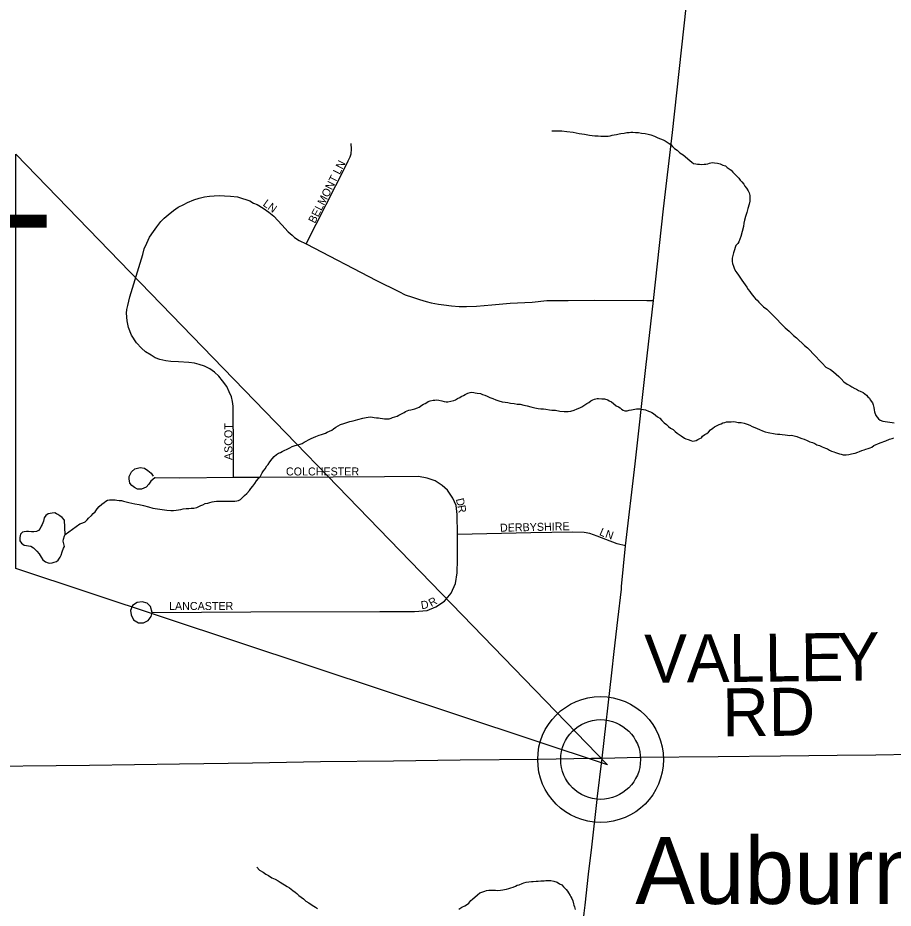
# Model space of a CAD drawing. Extents: x -10.1 to 68, y -9.5 to 29.2.
# Drawn here: x 4.482 to 5.518, y 19.418 to 20.471 of the extents above; entities that cross this region are included whole.
import ezdxf

# ---------------------------------------------------------------- set-up
doc = ezdxf.new("R2010")
doc.units = 0
for name, color, linetype in [('GM_X_County_Road', 7, 'Continuous'), ('GM_X_Minor_Lake', 7, 'Continuous'), ('GM_X_Minor_River', 7, 'Continuous'), ('GM_X_State_Route', 7, 'Continuous'), ('GM_X_Township_Road', 7, 'Continuous'), ('GM_X_Township_Road_Text', 7, 'Continuous'), ('GM_X_Township_Subdivision', 7, 'Continuous'), ('GM_X_Township_Subdivision_Text', 7, 'Continuous'), ('GM_X_Unincorporated', 7, 'Continuous'), ('GM_X_Unincorporated_Text', 7, 'Continuous'), ('SH_Data', 7, 'Continuous'), ('SH_Text', 7, 'Continuous')]:
    doc.layers.add(name, color=color, linetype=linetype)

msp = doc.modelspace()

# ---------------------------------------------------------------- linework, layer by layer
at = {"layer": 'GM_X_County_Road'}
msp.add_lwpolyline([(4.4092, 19.5855), (4.5666, 19.5872), (4.6732, 19.5887), (4.7595, 19.5899), (4.8399, 19.5914), (4.9265, 19.5923), (5.0054, 19.5936), (5.0981, 19.5945), (5.1608, 19.5955), (5.1733, 19.5955)], dxfattribs=at)
at = {"layer": 'GM_X_Minor_Lake'}
for points in [[(4.5372, 19.877), (4.5345, 19.88), (4.5318, 19.8822), (4.5295, 19.8836), (4.5276, 19.8847), (4.5256, 19.8858), (4.5226, 19.8854), (4.5177, 19.8845), (4.5151, 19.8826), (4.5132, 19.8799), (4.5122, 19.8757), (4.5107, 19.8718), (4.5096, 19.8699), (4.5085, 19.8672), (4.5063, 19.8649), (4.5041, 19.8637), (4.501, 19.8633), (4.498, 19.8632), (4.4945, 19.8635), (4.4923, 19.8638), (4.4896, 19.8634), (4.4877, 19.863), (4.4851, 19.8603), (4.4844, 19.8564), (4.4845, 19.8526), (4.4865, 19.85), (4.4896, 19.8474)], [(4.5372, 19.877), (4.5345, 19.88), (4.5318, 19.8822), (4.5295, 19.8836), (4.5276, 19.8847), (4.5256, 19.8858), (4.5226, 19.8854), (4.5177, 19.8845), (4.5151, 19.8826), (4.5132, 19.8799), (4.5122, 19.8757), (4.5107, 19.8718), (4.5096, 19.8699), (4.5085, 19.8672), (4.5063, 19.8649), (4.5041, 19.8637), (4.501, 19.8633), (4.498, 19.8632), (4.4945, 19.8635), (4.4923, 19.8638), (4.4896, 19.8634), (4.4877, 19.863), (4.4851, 19.8603), (4.4844, 19.8564), (4.4845, 19.8526), (4.4865, 19.85), (4.4896, 19.8474), (4.4972, 19.8461), (4.5007, 19.8443), (4.5026, 19.8424), (4.5045, 19.8405), (4.5073, 19.8372), (4.5085, 19.8353), (4.5096, 19.8331), (4.5116, 19.8301), (4.5147, 19.8278), (4.5178, 19.8264), (4.5197, 19.826), (4.5227, 19.8265), (4.525, 19.8273), (4.5276, 19.8281), (4.5299, 19.8297), (4.5321, 19.8332), (4.5332, 19.8358), (4.5346, 19.8397), (4.536, 19.8439), (4.5371, 19.8458), (4.5363, 19.8492), (4.5355, 19.8522), (4.5362, 19.8545), (4.5373, 19.8583), (4.538, 19.8599), (4.5372, 19.877)], [(4.4896, 19.8474), (4.4972, 19.8461), (4.5007, 19.8443), (4.5026, 19.8424), (4.5045, 19.8405), (4.5073, 19.8372), (4.5085, 19.8353), (4.5096, 19.8331), (4.5116, 19.8301), (4.5147, 19.8278), (4.5178, 19.8264), (4.5197, 19.826), (4.5227, 19.8265), (4.525, 19.8273), (4.5276, 19.8281), (4.5299, 19.8297), (4.5321, 19.8332), (4.5332, 19.8358), (4.5346, 19.8397), (4.536, 19.8439), (4.5371, 19.8458), (4.5363, 19.8492), (4.5355, 19.8522), (4.5362, 19.8545), (4.5373, 19.8583), (4.538, 19.8599), (4.5372, 19.877)]]:
    msp.add_lwpolyline(points, dxfattribs=at)
at = {"layer": 'GM_X_Minor_River'}
for points in [[(5.1136, 20.3376), (5.1163, 20.3376), (5.1201, 20.3377), (5.1254, 20.3374), (5.1315, 20.3368), (5.1388, 20.3358), (5.146, 20.3345), (5.1525, 20.3335), (5.1583, 20.3324), (5.1647, 20.3318), (5.1685, 20.3315), (5.1716, 20.3312), (5.1746, 20.3313), (5.1773, 20.3313), (5.1803, 20.3314), (5.1826, 20.3318), (5.1853, 20.3323), (5.1875, 20.3327), (5.1902, 20.3331), (5.1932, 20.334), (5.1955, 20.3344), (5.1993, 20.3349), (5.2023, 20.3357), (5.2054, 20.3357), (5.2073, 20.3358), (5.2095, 20.3358), (5.2126, 20.3355), (5.2164, 20.3356), (5.2198, 20.3349), (5.224, 20.3343), (5.2278, 20.3336), (5.2309, 20.3329), (5.2351, 20.3311), (5.239, 20.3293), (5.2424, 20.3282), (5.2455, 20.3267), (5.2478, 20.3256), (5.2501, 20.3242), (5.2524, 20.3227), (5.2544, 20.3212), (5.2563, 20.319), (5.259, 20.3168), (5.2621, 20.3146), (5.2652, 20.3116), (5.2691, 20.309), (5.2768, 20.3023), (5.2795, 20.3005), (5.2815, 20.299), (5.2841, 20.2983), (5.286, 20.298), (5.2883, 20.298), (5.2906, 20.2977), (5.294, 20.2981), (5.2959, 20.2982), (5.2982, 20.2986), (5.3001, 20.2994), (5.302, 20.2998), (5.3039, 20.2999), (5.3062, 20.2996), (5.3096, 20.2992), (5.313, 20.2986), (5.3161, 20.2971), (5.3192, 20.296), (5.3211, 20.2942), (5.3234, 20.2927), (5.3258, 20.2909), (5.3277, 20.2886), (5.33, 20.2868), (5.3331, 20.2834), (5.3351, 20.2816), (5.3367, 20.2793), (5.3386, 20.2771), (5.3409, 20.2745), (5.3421, 20.2722), (5.3441, 20.2696), (5.3461, 20.2666), (5.3472, 20.2643), (5.3481, 20.2609), (5.3481, 20.2583), (5.3478, 20.2545), (5.3472, 20.2507), (5.3457, 20.2457), (5.3443, 20.2411), (5.3429, 20.2361), (5.3418, 20.2319), (5.3408, 20.2285), (5.3405, 20.2243), (5.3373, 20.2124), (5.3362, 20.2094), (5.3348, 20.2063), (5.3337, 20.2044), (5.3315, 20.2017), (5.3307, 20.1994), (5.3297, 20.1967), (5.3286, 20.1932), (5.3279, 20.1902), (5.3272, 20.1871), (5.3269, 20.1848), (5.3269, 20.183), (5.3273, 20.1807), (5.3286, 20.1773)], [(5.3286, 20.1773), (5.3298, 20.1739), (5.3313, 20.1713), (5.3325, 20.1694), (5.3345, 20.1668), (5.3368, 20.1634), (5.3384, 20.1608), (5.3404, 20.1582), (5.3423, 20.1552), (5.3443, 20.1525), (5.3459, 20.1499), (5.3478, 20.1473), (5.3494, 20.1451), (5.351, 20.1432), (5.3525, 20.1413), (5.3545, 20.1387), (5.3568, 20.1372), (5.3587, 20.135), (5.3611, 20.1324), (5.3642, 20.1294), (5.3681, 20.1265), (5.3716, 20.1231), (5.3754, 20.119), (5.3801, 20.1149), (5.3848, 20.1097), (5.3898, 20.1045), (5.3945, 20.1004), (5.3995, 20.0956), (5.403, 20.0926), (5.4127, 20.0837), (5.4162, 20.0808), (5.4193, 20.0778), (5.4224, 20.0741), (5.4263, 20.0703), (5.4298, 20.0662), (5.4337, 20.0629), (5.438, 20.0581), (5.4434, 20.0551), (5.4469, 20.0525), (5.45, 20.0496), (5.4531, 20.047), (5.4562, 20.044), (5.4593, 20.0407), (5.4631, 20.0377), (5.4662, 20.0362), (5.4685, 20.0348), (5.472, 20.0329), (5.4743, 20.0319), (5.4766, 20.0304), (5.4785, 20.0297), (5.482, 20.0282), (5.4839, 20.0264), (5.4859, 20.0249), (5.4874, 20.023), (5.4894, 20.0212), (5.4905, 20.0193), (5.4929, 20.0159), (5.4937, 20.0133), (5.4945, 20.0103), (5.495, 20.0076), (5.4954, 20.0053), (5.497, 20.0008), (5.4986, 19.9989), (5.5002, 19.9967), (5.5021, 19.9952), (5.5052, 19.9941), (5.5136, 19.9928), (5.5162, 19.9925), (5.5189, 19.9922)], [(4.8383, 19.9774), (4.8413, 19.9782), (4.8436, 19.979), (4.8458, 19.9798), (4.8481, 19.981), (4.8507, 19.9822), (4.8534, 19.9834), (4.8556, 19.985), (4.8582, 19.9869), (4.8609, 19.9885), (4.8639, 19.9901), (4.8677, 19.9913), (4.8699, 19.9921), (4.8722, 19.9929), (4.8748, 19.9938), (4.8767, 19.9942), (4.8786, 19.9946), (4.8816, 19.9954), (4.8843, 19.9959), (4.89, 19.9975), (4.8922, 19.9979), (4.8941, 19.9984), (4.8964, 19.9988), (4.8998, 19.9992), (4.9017, 19.9989), (4.9036, 19.9986), (4.9063, 19.9982), (4.9086, 19.9979), (4.9105, 19.9976), (4.9136, 19.9973), (4.9159, 19.9969), (4.9185, 19.997), (4.9212, 19.997), (4.9235, 19.9975), (4.9253, 19.9983), (4.928, 19.9991), (4.9306, 19.9999), (4.9329, 20.0011), (4.9366, 20.0031), (4.9389, 20.0043), (4.9408, 20.0054), (4.9427, 20.0062), (4.9445, 20.007), (4.9468, 20.0075), (4.9487, 20.0079), (4.9517, 20.0087), (4.9548, 20.0099), (4.9566, 20.0107), (4.96, 20.0131), (4.9619, 20.0143), (4.9638, 20.0151), (4.9657, 20.0162), (4.9675, 20.0174), (4.9698, 20.0182), (4.9732, 20.0191), (4.9755, 20.0191), (4.9778, 20.0192), (4.9801, 20.0188), (4.9835, 20.0182), (4.9862, 20.0175), (4.9888, 20.0171), (4.9908, 20.0168), (4.9976, 20.0185), (4.9998, 20.0193), (5.0021, 20.0208), (5.0047, 20.022), (5.0066, 20.0232), (5.0092, 20.0244), (5.0111, 20.0256), (5.0145, 20.0272), (5.0171, 20.028), (5.019, 20.0284), (5.0213, 20.0281), (5.0232, 20.0278), (5.0255, 20.0274), (5.0293, 20.0268), (5.0316, 20.0257), (5.0343, 20.025), (5.0374, 20.0235), (5.0405, 20.0221), (5.0439, 20.021), (5.0474, 20.0192), (5.0512, 20.0181), (5.055, 20.0171), (5.0585, 20.0164), (5.0615, 20.016), (5.065, 20.0154), (5.0692, 20.0151), (5.0726, 20.0144), (5.0764, 20.0141), (5.0806, 20.013), (5.0844, 20.0124), (5.089, 20.0109), (5.0936, 20.0099), (5.0974, 20.0092), (5.1009, 20.0089), (5.1039, 20.0086), (5.1066, 20.0083), (5.1108, 20.0076), (5.1138, 20.0073), (5.118, 20.007)], [(5.118, 20.007), (5.123, 20.006), (5.1283, 20.0057), (5.1329, 20.0054), (5.1363, 20.0059), (5.1401, 20.0071), (5.1438, 20.0087), (5.1469, 20.0099), (5.1491, 20.0111), (5.1551, 20.015), (5.1574, 20.0162), (5.16, 20.0182), (5.1623, 20.0194), (5.1641, 20.0202), (5.1672, 20.021), (5.1691, 20.021), (5.1729, 20.0207), (5.1759, 20.0204), (5.1798, 20.0194), (5.1817, 20.0183), (5.1844, 20.0168), (5.1867, 20.015), (5.1898, 20.0124), (5.1925, 20.0109), (5.1944, 20.0098), (5.1963, 20.0083), (5.1983, 20.0072), (5.2002, 20.0065), (5.2029, 20.0062), (5.2051, 20.007), (5.2078, 20.0074), (5.2101, 20.0079), (5.2119, 20.0083), (5.2138, 20.0087), (5.2157, 20.0088), (5.218, 20.0088), (5.2199, 20.0085), (5.2222, 20.0081), (5.2245, 20.0074), (5.228, 20.006), (5.2303, 20.0053), (5.2322, 20.0042), (5.2341, 20.0031), (5.2364, 20.0012), (5.2388, 19.9994), (5.2415, 19.9975), (5.2438, 19.9949), (5.2465, 19.9923), (5.2492, 19.9901), (5.2519, 19.9879), (5.2543, 19.9857), (5.2573, 19.9842), (5.2597, 19.982), (5.262, 19.9801), (5.2643, 19.9783), (5.2666, 19.9768), (5.2705, 19.9742), (5.2724, 19.9731), (5.2751, 19.9724), (5.2782, 19.9714), (5.2801, 19.9706), (5.2827, 19.9707), (5.2846, 19.9711), (5.2865, 19.9723), (5.2888, 19.9735), (5.2907, 19.9743), (5.2921, 19.9762), (5.2948, 19.9782), (5.297, 19.9797), (5.2989, 19.9813), (5.3015, 19.984), (5.3041, 19.986), (5.3063, 19.9875), (5.3094, 19.9891), (5.3116, 19.9903), (5.3139, 19.9911), (5.3161, 19.9923), (5.3184, 19.9927), (5.3203, 19.9932), (5.3237, 19.9932), (5.326, 19.9933), (5.3287, 19.9937), (5.3309, 19.9934), (5.334, 19.9927), (5.3378, 19.9924), (5.3413, 19.9917), (5.3447, 19.9907), (5.3478, 19.9892), (5.3509, 19.9878), (5.3539, 19.9867), (5.3566, 19.9856), (5.3593, 19.9841), (5.3628, 19.9827), (5.3662, 19.9816), (5.3696, 19.9806), (5.378, 19.9792), (5.3807, 19.9789), (5.3834, 19.9786), (5.3864, 19.9783), (5.3899, 19.978), (5.3925, 19.9776)], [(4.538, 19.8599), (4.5552, 19.8728), (4.559, 19.874), (4.5616, 19.8752), (4.5639, 19.8776), (4.5657, 19.8795), (4.5691, 19.8826), (4.5713, 19.8849), (4.5736, 19.8869), (4.5758, 19.8903), (4.5784, 19.8931), (4.5814, 19.8958), (4.584, 19.8981), (4.5862, 19.8993), (4.5881, 19.9005), (4.5904, 19.9009), (4.593, 19.901), (4.5949, 19.901), (4.5972, 19.9011), (4.5991, 19.9007), (4.6018, 19.9004), (4.6045, 19.9001), (4.6071, 19.8994), (4.6102, 19.8987), (4.6133, 19.898), (4.6167, 19.8973), (4.6205, 19.8963), (4.6255, 19.8956), (4.6308, 19.8942), (4.6366, 19.8928), (4.6419, 19.8914), (4.6583, 19.8887), (4.6629, 19.8884), (4.6663, 19.8885), (4.6694, 19.889), (4.672, 19.8894), (4.6747, 19.8898), (4.6777, 19.8903), (4.6811, 19.8907), (4.6842, 19.8908), (4.6872, 19.8913), (4.6902, 19.8913), (4.6936, 19.8921), (4.6963, 19.8933), (4.6986, 19.8942), (4.7008, 19.8953), (4.7038, 19.8966), (4.7069, 19.897), (4.7091, 19.8978), (4.7118, 19.8986), (4.7144, 19.8991), (4.7171, 19.8995), (4.7197, 19.8996), (4.7232, 19.8996), (4.7285, 19.8994), (4.7323, 19.8995), (4.7357, 19.8995), (4.7388, 19.8996), (4.741, 19.9), (4.7429, 19.9004), (4.7456, 19.9016), (4.7478, 19.904), (4.75, 19.9063), (4.753, 19.9086), (4.756, 19.9121), (4.7578, 19.9144), (4.7601, 19.9172), (4.7623, 19.9202), (4.7645, 19.9237), (4.7667, 19.9264), (4.7686, 19.9284), (4.7697, 19.9307), (4.7711, 19.933), (4.7726, 19.9353), (4.7745, 19.9376), (4.7767, 19.9411), (4.7782, 19.943), (4.78, 19.9461), (4.783, 19.9496), (4.7852, 19.9523), (4.7882, 19.9546), (4.7904, 19.9562), (4.7927, 19.957), (4.7946, 19.9582), (4.7972, 19.9594), (4.8006, 19.961), (4.8036, 19.9626), (4.8066, 19.9641), (4.81, 19.9654), (4.8134, 19.9662), (4.8161, 19.967), (4.8183, 19.9678), (4.8206, 19.9694), (4.8232, 19.9706), (4.8258, 19.9722), (4.8292, 19.9738), (4.8345, 19.9758), (4.8383, 19.9774)], [(5.3925, 19.9776), (5.3948, 19.9773), (5.3971, 19.9774), (5.4005, 19.9767), (5.4036, 19.976), (5.4063, 19.9749), (5.4093, 19.9738), (5.4124, 19.9727), (5.4159, 19.9713), (5.4189, 19.9698), (5.422, 19.9688), (5.4247, 19.9677), (5.4274, 19.9662), (5.4305, 19.9652), (5.4335, 19.9637), (5.4374, 19.9623), (5.4397, 19.9612), (5.4424, 19.9597), (5.4447, 19.9586), (5.4473, 19.9579), (5.4493, 19.9572), (5.4516, 19.9561), (5.4539, 19.9554), (5.4562, 19.9551), (5.4585, 19.9544), (5.4619, 19.9541), (5.4649, 19.9545), (5.4683, 19.9553), (5.4702, 19.9558), (5.4725, 19.9562), (5.4759, 19.9574), (5.4778, 19.9582), (5.4804, 19.9594), (5.4831, 19.9602), (5.4853, 19.961), (5.488, 19.9618), (5.4902, 19.9627), (5.4921, 19.9635), (5.4947, 19.9654), (5.5023, 19.9686), (5.5087, 19.971), (5.5132, 19.9727), (5.5162, 19.9735), (5.5185, 19.9743)], [(4.7647, 19.4665), (4.7678, 19.4632), (4.7721, 19.4606), (4.7752, 19.4584), (4.7786, 19.4566), (4.7825, 19.454), (4.7863, 19.4522), (4.7898, 19.4504), (4.7925, 19.4489), (4.8006, 19.4438), (4.8033, 19.4423), (4.8052, 19.4404), (4.8075, 19.439), (4.8099, 19.4371), (4.8122, 19.4353), (4.8145, 19.433), (4.8172, 19.4312), (4.8199, 19.429), (4.8226, 19.4264), (4.8261, 19.4242), (4.8292, 19.4223), (4.8323, 19.4205), (4.8342, 19.4194), (4.8365, 19.4175)], [(5.0472, 19.4392), (5.0495, 19.4389), (5.0529, 19.4393), (5.0559, 19.4398), (5.0578, 19.4402), (5.0601, 19.4406), (5.0627, 19.4415), (5.0654, 19.4423), (5.068, 19.4431), (5.0707, 19.4443), (5.0729, 19.4451), (5.0752, 19.4455), (5.0786, 19.4471), (5.0805, 19.4479), (5.0835, 19.4488), (5.0865, 19.4492), (5.0896, 19.4496), (5.0918, 19.4497), (5.0953, 19.4501), (5.0975, 19.4502), (5.1006, 19.4503), (5.1025, 19.4503), (5.1048, 19.4504), (5.1067, 19.4508), (5.1086, 19.4508), (5.1105, 19.4509), (5.1124, 19.4509), (5.1162, 19.4502), (5.12, 19.4488), (5.1227, 19.4469), (5.1254, 19.4455), (5.1274, 19.4432), (5.1305, 19.4403), (5.1324, 19.438), (5.1336, 19.4362), (5.1356, 19.4332), (5.1364, 19.4313), (5.1375, 19.4294), (5.1384, 19.4268), (5.1392, 19.4234), (5.1396, 19.4215), (5.1404, 19.4196), (5.1412, 19.4166)], [(5.0039, 19.417), (5.0073, 19.4194), (5.011, 19.421), (5.0129, 19.4221), (5.0155, 19.4241), (5.0181, 19.4272), (5.02, 19.4288), (5.0256, 19.4338), (5.0286, 19.4362), (5.032, 19.4374), (5.0346, 19.4382), (5.0365, 19.439), (5.0392, 19.4394), (5.0422, 19.4395), (5.0445, 19.4392), (5.0472, 19.4392)]]:
    msp.add_lwpolyline(points, dxfattribs=at)
at = {"layer": 'GM_X_State_Route'}
for points in [[(5.1963, 19.7984), (5.201, 19.8468), (5.2122, 19.9435), (5.2251, 20.0575), (5.2339, 20.137), (5.2458, 20.2452), (5.2563, 20.3354), (5.2755, 20.5089), (5.297, 20.7013), (5.3191, 20.9)], [(5.1733, 19.5955), (5.1846, 19.6963), (5.1875, 19.7218), (5.1918, 19.7593), (5.196, 19.7954), (5.1963, 19.7984)]]:
    msp.add_lwpolyline(points, dxfattribs=at)
at = {"layer": 'GM_X_Township_Road'}
msp.add_lwpolyline([(5.1733, 19.5955), (5.2177, 19.5965), (5.3104, 19.5974), (5.3844, 19.5982), (5.4511, 19.599), (5.497, 19.5994), (5.5393, 19.6004), (5.5509, 19.6006), (5.5606, 19.6011), (5.5667, 19.603), (5.5747, 19.6073)], dxfattribs=at)
at = {"layer": 'GM_X_Township_Subdivision'}
for points in [[(4.8231, 20.2038), (4.8701, 20.2962), (4.8728, 20.3019), (4.875, 20.3066), (4.8762, 20.3105), (4.8769, 20.3157), (4.8762, 20.3225)], [(4.7372, 19.9273), (4.7372, 19.9675), (4.7368, 20.0023), (4.7367, 20.0118), (4.736, 20.0175), (4.7346, 20.023), (4.7322, 20.0289), (4.7291, 20.0351), (4.7243, 20.0418), (4.7198, 20.0475), (4.7148, 20.0522), (4.7091, 20.056), (4.7029, 20.0591), (4.6967, 20.0613), (4.691, 20.0627), (4.6844, 20.0636), (4.672, 20.0644), (4.6629, 20.0648), (4.657, 20.0653), (4.6501, 20.0672), (4.6446, 20.0691), (4.6396, 20.0722), (4.6332, 20.0763), (4.6282, 20.0805), (4.6225, 20.0867), (4.6165, 20.0958), (4.613, 20.1048), (4.6113, 20.1129), (4.6106, 20.1217), (4.6108, 20.1262), (4.612, 20.131), (4.6146, 20.141), (4.6299, 20.1912), (4.6315, 20.1981), (4.6346, 20.2048), (4.6377, 20.2119), (4.6425, 20.2186), (4.6465, 20.2241), (4.651, 20.2302), (4.6551, 20.2341), (4.6598, 20.2381), (4.6663, 20.2433), (4.6715, 20.2471), (4.6784, 20.2505), (4.6827, 20.2529), (4.6901, 20.256), (4.6967, 20.2579), (4.7029, 20.2593), (4.7089, 20.2602), (4.7141, 20.2607), (4.7201, 20.2609), (4.7265, 20.2607), (4.7336, 20.2602), (4.7417, 20.2593), (4.7477, 20.2576), (4.7519, 20.2564), (4.7565, 20.2548), (4.7608, 20.2521), (4.765, 20.2502), (4.7722, 20.2462), (4.7791, 20.2414), (4.785, 20.2364), (4.7943, 20.2262), (4.8019, 20.2181), (4.8064, 20.2141), (4.8095, 20.2114), (4.8148, 20.2079), (4.8231, 20.2038), (4.9062, 20.1605), (4.9326, 20.1474), (4.9402, 20.1436), (4.949, 20.1408), (4.9571, 20.1379), (4.9652, 20.1355), (4.9711, 20.1341), (4.9795, 20.1327), (4.9861, 20.1317), (4.9952, 20.1305), (5.004, 20.1298), (5.0128, 20.1296), (5.0245, 20.1303), (5.0428, 20.1317), (5.0644, 20.1336), (5.0904, 20.135), (5.108, 20.137), (5.117, 20.137), (5.133, 20.137), (5.1646, 20.1372), (5.226, 20.137), (5.2339, 20.137)], [(4.6445, 19.927), (4.6439, 19.927), (4.6394, 19.9231), (4.6368, 19.9195), (4.6339, 19.9159), (4.6282, 19.9137), (4.6237, 19.9138), (4.6201, 19.9155), (4.6167, 19.918), (4.6145, 19.9209), (4.6136, 19.9259), (4.6138, 19.9286), (4.6163, 19.9343), (4.6205, 19.9379), (4.6267, 19.9394), (4.632, 19.9384), (4.6359, 19.9358), (4.6396, 19.9325), (4.642, 19.9289)], [(5.0021, 19.8602), (5.0018, 19.8837), (5.0004, 19.8944), (4.9966, 19.9032), (4.9904, 19.9125), (4.9838, 19.9181), (4.9759, 19.9235), (4.9664, 19.9268), (4.9561, 19.9285), (4.9156, 19.9282), (4.8552, 19.9278), (4.7677, 19.9275), (4.7372, 19.9273), (4.6736, 19.9265), (4.6445, 19.927)], [(5.201, 19.8468), (5.1909, 19.8491), (5.1775, 19.854), (5.1673, 19.8582), (5.1587, 19.8611), (5.1518, 19.8625), (5.1385, 19.8628), (5.0887, 19.8619), (5.0021, 19.8602)], [(4.641, 19.768), (4.6389, 19.775), (4.6351, 19.779), (4.6291, 19.7804), (4.623, 19.7795), (4.6175, 19.7762), (4.6151, 19.7702), (4.6161, 19.7652), (4.6187, 19.7593), (4.6249, 19.7557), (4.6306, 19.7557), (4.636, 19.7583), (4.6396, 19.7631), (4.641, 19.768), (4.7577, 19.7684), (4.9102, 19.7688), (4.9514, 19.769), (4.9661, 19.7702), (4.9766, 19.7747), (4.9866, 19.7811), (4.9945, 19.7907), (4.9999, 19.8023), (5.0016, 19.8149), (5.0021, 19.8304), (5.0021, 19.8602)]]:
    msp.add_lwpolyline(points, dxfattribs=at)
at = {"layer": 'GM_X_Unincorporated'}
for radius in [0.0744, 0.0472]:
    msp.add_circle((5.1714, 19.5939), radius, dxfattribs=at)
at = {"layer": 'SH_Data'}
for points in [[(5.1675, 19.5473), (5.1733, 19.5955)], [(5.1531, 19.4217), (5.1571, 19.4582), (5.1611, 19.4901), (5.1674, 19.5465), (5.1675, 19.5473)], [(5.1465, 19.3606), (5.1478, 19.3745), (5.1488, 19.3847), (5.152, 19.4121), (5.1531, 19.4217)]]:
    msp.add_lwpolyline(points, dxfattribs=at)
at = {"layer": 'SH_Text'}
msp.add_lwpolyline([(5.1794, 19.5875), (4.4795, 19.82), (4.4795, 20.31)], close=True, dxfattribs=at)

# ---------------------------------------------------------------- texts
at = {"layer": 'GM_X_Township_Road_Text'}
for s, height, rotation, p in [('V', 0.0568, 0.5319, (5.2234, 19.6847)), ('A', 0.0568, 0.5319, (5.2734, 19.6851)), ('L', 0.0568, 0.5271, (5.3234, 19.6856)), ('L', 0.0568, 0.5314, (5.3659, 19.686)), ('E', 0.0568, 0.5314, (5.4084, 19.6864)), ('Y', 0.0568, 1.1717, (5.4516, 19.6868)), ('RD', 0.05682, 0.4936, (5.3157, 19.6213))]:
    msp.add_text(s, height=height, rotation=rotation, dxfattribs=at).set_placement(p)
at = {"layer": 'GM_X_Township_Subdivision_Text'}
for s, rotation, p in [('BELMONT LN', 63.1446, (4.8335, 20.2273)), ('LN', 323.7481, (4.7711, 20.2496)), ('ASCOT', 90, (4.7358, 19.9481)), ('COLCHESTER', 0, (4.7992, 19.9299)), ('D', 282.9864, (5.0001, 19.9019)), ('R', 280.8241, (5.0019, 19.8939)), ('DERBYSHIRE', 1.3187, (5.0525, 19.8633)), ('L', 336.7727, (5.1692, 19.8597)), ('N', 341.9236, (5.1762, 19.8568)), ('LANCASTER', 0, (4.6609, 19.7708)), ('D', 9.3509, (4.9596, 19.7716)), ('R', 29.7349, (4.9712, 19.7742))]:
    msp.add_text(s, height=0.00947, rotation=rotation, dxfattribs=at).set_placement(p)
at = {"layer": 'GM_X_Unincorporated_Text'}
msp.add_text('Auburn Corners', height=0.078977, rotation=0, dxfattribs=at).set_placement((5.2125, 19.4231))
at = {"layer": 'SH_Text'}
msp.add_text('END PROJECT', height=0.14, dxfattribs=at).set_placement((3.1993, 20.0985))

doc.saveas('drawing.dxf')
